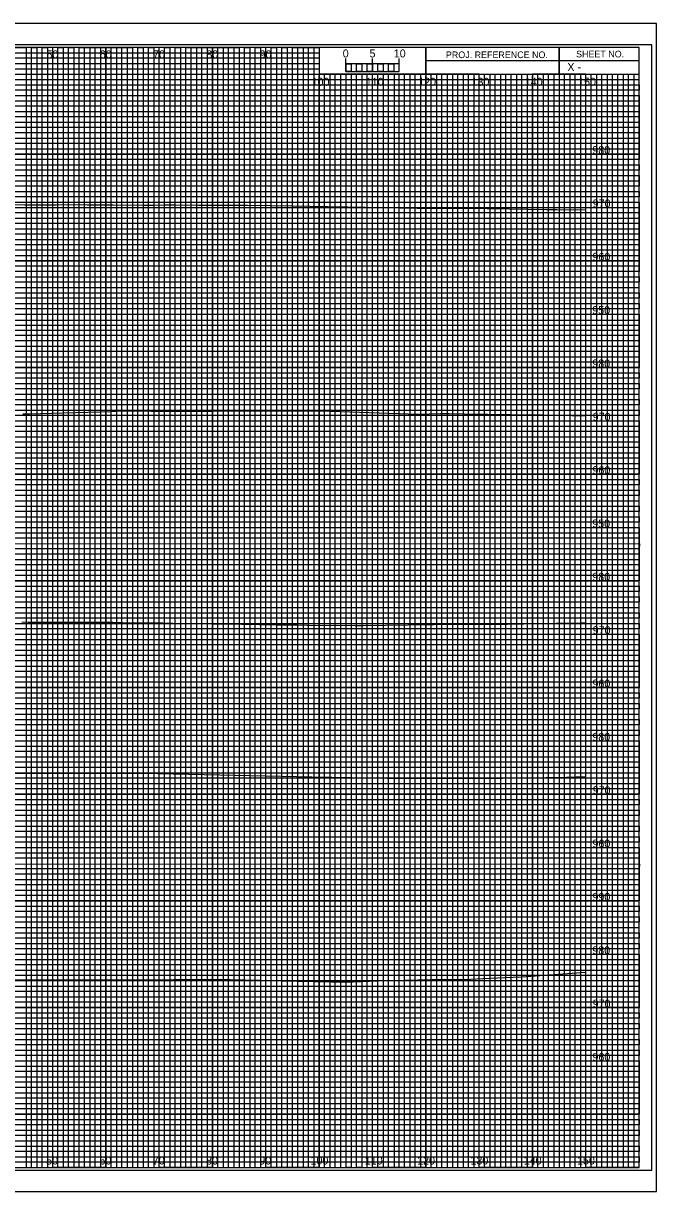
# Model space of a CAD drawing. Extents: x -13 to 760, y -5 to 1491.
# Drawn here: x 204.5 to 323.3, y 314.5 to 533.5 of the extents above; entities that cross this region are included whole.
import ezdxf

# ---------------------------------------------------------------- set-up
doc = ezdxf.new("R2010")
doc.units = 0
for name, color, linetype in [('Exist XS Ground Line', 7, 'Continuous'), ('Prop XS Elevation Labels', 7, 'Continuous'), ('Prop XS Offset Labels', 7, 'Continuous'), ('Sheet Cross Section CELL', 7, 'Continuous'), ('Sheet Cross Section Grid Major CELL', 7, 'Continuous'), ('Sheet Cross Section Grid Middle CELL', 7, 'Continuous'), ('Sheet Cross Section Grid Minor 1 CELL', 7, 'Continuous'), ('Sheet Cross Section Grid Minor 2 CELL', 7, 'Continuous'), ('Sheet Cross Section Scale CELL', 7, 'Continuous'), ('Sheet Cutting Line CELL', 7, 'Continuous'), ('Sheet DOT Grid CELL', 7, 'Continuous'), ('Sheet Plot Border Inside CELL', 7, 'Continuous'), ('Sheet Plot Border Outside CELL', 7, 'Continuous')]:
    doc.layers.add(name, color=color, linetype=linetype)

msp = doc.modelspace()

# ---------------------------------------------------------------- linework, layer by layer
at = {"layer": 'Exist XS Ground Line'}
for points in [[(202.88, 499.55), (204.75, 499.5), (206.74, 499.51), (210.68, 499.51), (214.94, 499.52), (216.5, 499.5), (217.94, 499.49), (219.17, 499.48), (220.13, 499.48), (221.36, 499.46), (226.92, 499.42), (229.08, 499.44), (231.04, 499.46), (232.82, 499.51), (237.39, 499.43), (241.03, 499.42), (243.02, 499.43), (243.42, 499.44), (246.57, 499.43), (255.04, 499.33), (261.56, 499.19), (265.31, 499.12), (271.92, 499.01), (278.4, 498.89), (282.15, 498.85), (291.48, 498.83), (292.39, 498.83), (295.64, 498.76), (302.62, 498.62), (304.57, 498.6), (310, 498.55)], [(202.88, 499.55), (204.75, 499.5), (206.74, 499.51), (210.68, 499.51), (214.94, 499.52), (216.5, 499.5), (217.94, 499.49), (219.17, 499.48), (220.13, 499.48), (221.36, 499.46), (226.92, 499.42), (229.08, 499.44), (231.04, 499.46), (232.82, 499.51), (237.39, 499.43), (241.03, 499.42), (243.02, 499.43), (243.42, 499.44), (246.57, 499.43), (255.04, 499.33), (261.56, 499.19), (265.31, 499.12), (271.92, 499.01), (278.4, 498.89), (282.15, 498.85), (291.48, 498.83), (292.39, 498.83), (295.64, 498.76), (302.62, 498.62), (304.57, 498.6), (310, 498.55)], [(204.4, 460.31), (205.65, 460.34), (209.75, 460.45), (218.84, 460.68), (220.94, 460.76), (223.32, 460.87), (224.87, 460.87), (226.48, 460.85), (228.46, 460.84), (229.33, 460.81), (229.71, 460.82), (231.78, 460.79), (237.68, 460.78), (239.04, 460.81), (240.03, 460.81), (260.29, 460.85), (278.51, 460.24), (282.74, 460.4), (284.4, 460.4), (287.25, 460.32), (295.94, 460.17), (297, 460.14), (297.06, 460.14), (297.47, 460.13), (297.58, 460.13), (299.47, 460.17), (310, 459.92)], [(204.4, 460.31), (205.65, 460.34), (209.75, 460.45), (218.84, 460.68), (220.94, 460.76), (223.32, 460.87), (224.87, 460.87), (226.48, 460.85), (228.46, 460.84), (229.33, 460.81), (229.71, 460.82), (231.78, 460.79), (237.68, 460.78), (239.04, 460.81), (240.03, 460.81), (260.29, 460.85), (278.51, 460.24), (282.74, 460.4), (284.4, 460.4), (287.25, 460.32), (295.94, 460.17), (297, 460.14), (297.06, 460.14), (297.47, 460.13), (297.58, 460.13), (299.47, 460.17), (310, 459.92)], [(204.23, 421.29), (205.43, 421.26), (206.07, 421.26), (208.42, 421.25), (210.37, 421.25), (220.94, 421.27), (221.29, 421.26), (223.07, 421.22), (230.67, 421.12), (234.42, 421.03), (240.01, 420.97), (242.02, 420.93), (248.71, 420.81), (252.08, 420.76), (255.81, 420.73), (257.74, 420.72), (266.77, 420.62), (268.1, 420.61), (268.11, 420.61), (268.22, 420.61), (276.66, 420.73), (279.91, 420.79), (281.51, 420.81), (289.1, 420.89), (289.26, 420.89), (289.67, 420.89), (294.57, 420.87), (295.35, 420.89), (301.54, 420.99), (304.46, 421.05), (309.11, 421.14), (310, 421.16)], [(204.23, 421.29), (205.43, 421.26), (206.07, 421.26), (208.42, 421.25), (210.37, 421.25), (220.94, 421.27), (221.29, 421.26), (223.07, 421.22), (230.67, 421.12), (234.42, 421.03), (240.01, 420.97), (242.02, 420.93), (248.71, 420.81), (252.08, 420.76), (255.81, 420.73), (257.74, 420.72), (266.77, 420.62), (268.1, 420.61), (268.11, 420.61), (268.22, 420.61), (276.66, 420.73), (279.91, 420.79), (281.51, 420.81), (289.1, 420.89), (289.26, 420.89), (289.67, 420.89), (294.57, 420.87), (295.35, 420.89), (301.54, 420.99), (304.46, 421.05), (309.11, 421.14), (310, 421.16)], [(202.25, 392.89), (210.98, 392.94), (212.48, 392.95), (213.44, 392.96), (222.72, 392.98), (226.78, 392.95), (241.38, 392.64), (258.63, 392.27), (269.93, 392.07), (272.7, 392.04), (274.73, 392.04), (284.13, 392.03), (289.5, 392.01), (294.36, 392.01), (302.58, 392.12), (304.6, 392.15), (310, 392.31)], [(202.25, 392.89), (210.98, 392.94), (212.48, 392.95), (213.44, 392.96), (222.72, 392.98), (226.78, 392.95), (241.38, 392.64), (258.63, 392.27), (269.93, 392.07), (272.7, 392.04), (274.73, 392.04), (284.13, 392.03), (289.5, 392.01), (294.36, 392.01), (302.58, 392.12), (304.6, 392.15), (310, 392.31)], [(202.9, 354.27), (210.32, 354.23), (213.14, 354.23), (223.26, 354.22), (223.36, 354.22), (223.38, 354.22), (223.39, 354.22), (232.69, 354.26), (234.72, 354.26), (241.91, 354.28), (243.31, 354.25), (248.98, 354.12), (249.03, 354.12), (252.97, 354.02), (262.33, 353.82), (262.78, 353.83), (266.38, 353.85), (270.96, 354.02), (280.98, 354.24), (282.58, 354.25), (288.37, 354.31), (290.72, 354.44), (294.85, 354.64), (297.94, 354.79), (310, 355.64)], [(202.9, 354.27), (210.32, 354.23), (213.14, 354.23), (223.26, 354.22), (223.36, 354.22), (223.38, 354.22), (223.39, 354.22), (232.69, 354.26), (234.72, 354.26), (241.91, 354.28), (243.31, 354.25), (248.98, 354.12), (249.03, 354.12), (252.97, 354.02), (262.33, 353.82), (262.78, 353.83), (266.38, 353.85), (270.96, 354.02), (280.98, 354.24), (282.58, 354.25), (288.37, 354.31), (290.72, 354.44), (294.85, 354.64), (297.94, 354.79), (310, 355.64)]]:
    msp.add_lwpolyline(points, dxfattribs=at)
at = {"layer": 'Sheet Cross Section CELL'}
for p, q in [((305, 529), (305, 524)), ((305, 524), (305, 529)), ((280, 526.5), (280, 524)), ((320, 526.49), (280, 526.49)), ((280, 524), (320, 524))]:
    msp.add_line(p, q, dxfattribs=at)
for points in [[(320, 529), (0, 529), (0, 319), (320, 319)], [(280, 529), (260, 529), (260, 524.03), (280, 524.03)], [(320, 529), (280, 529), (280, 524), (320, 524)]]:
    msp.add_lwpolyline(points, close=True, dxfattribs=at)
at = {"layer": 'Sheet Cross Section Grid Major CELL'}
for p, q in [((210, 529), (200, 529)), ((210, 319), (210, 529)), ((230, 529), (220, 529)), ((220, 529), (220, 319)), ((230, 319), (230, 529)), ((250, 529), (240, 529)), ((240, 529), (240, 319)), ((250, 319), (250, 529)), ((260, 529), (260, 319)), ((270, 319), (270, 524)), ((290, 524), (280, 524)), ((280, 524), (280, 319)), ((290, 319), (290, 524)), ((310, 524), (300, 524)), ((300, 524), (300, 319)), ((310, 319), (310, 524)), ((220, 319), (210, 319)), ((240, 319), (230, 319)), ((260, 319), (250, 319)), ((280, 319), (270, 319)), ((300, 319), (290, 319)), ((320, 319), (310, 319)), ((320, 319), (320, 319))]:
    msp.add_line(p, q, dxfattribs=at)
for points in [[(0, 519), (320, 519), (320, 509), (0, 509)], [(0, 499), (320, 499), (320, 489), (0, 489)], [(0, 479), (320, 479), (320, 469), (0, 469)], [(0, 459), (320, 459), (320, 449), (0, 449)], [(0, 439), (320, 439), (320, 429), (0, 429)], [(0, 419), (320, 419), (320, 409), (0, 409)], [(0, 399), (320, 399), (320, 389), (0, 389)], [(0, 379), (320, 379), (320, 369), (0, 369)], [(0, 359), (320, 359), (320, 349), (0, 349)], [(0, 339), (320, 339), (320, 329), (0, 329)]]:
    msp.add_lwpolyline(points, dxfattribs=at)
at = {"layer": 'Sheet Cross Section Grid Middle CELL'}
for points in [[(195, 529), (205, 529), (205, 319), (215, 319), (215, 529), (225, 529), (225, 319), (235, 319), (235, 529), (245, 529), (245, 319), (255, 319), (255, 529), (259.93, 529), (260, 529), (260, 524), (264.99, 524), (264.99, 319), (275, 319), (275, 524), (285, 524), (285, 319), (295, 319), (295, 524), (305, 524), (305, 319), (315, 319), (315, 524)], [(0, 524), (275, 524)], [(0, 504), (320, 504), (320, 514), (0, 514)], [(0, 484), (320, 484), (320, 494), (0, 494)], [(0, 464), (320, 464), (320, 474), (0, 474)], [(0, 444), (320, 444), (320, 454), (0, 454)], [(0, 424), (320, 424), (320, 434), (0, 434)], [(0, 404), (320, 404), (320, 414), (0, 414)], [(0, 384), (320, 384), (320, 394), (0, 394)], [(0, 364), (320, 364), (320, 374), (0, 374)], [(0, 344), (320, 344), (320, 354), (0, 354)], [(0, 324), (320, 324), (320, 334), (0, 334)]]:
    msp.add_lwpolyline(points, dxfattribs=at)
at = {"layer": 'Sheet Cross Section Grid Minor 1 CELL'}
for p, q in [((0, 528), (260, 528)), ((260, 528), (260, 526.98)), ((260, 526.98), (0, 526.98)), ((0, 526), (260, 526)), ((260, 526), (260, 524.89)), ((260, 524.89), (0, 524.89)), ((0, 523), (320, 523))]:
    msp.add_line(p, q, dxfattribs=at)
for points in [[(0, 522), (270, 522), (320, 522), (320, 521), (0, 521)], [(0, 520), (320, 520), (320, 518), (0, 518)], [(0, 517), (320, 517), (320, 516), (0, 515.98)], [(0, 515), (320, 515), (320, 513), (0, 513)], [(0, 512), (320, 512), (320, 511), (0, 511)], [(0, 510), (320, 510), (320, 508), (0, 508)], [(0, 507), (320, 507), (320, 506), (0, 506)], [(0, 505), (320, 505), (320, 503), (0, 503)], [(0, 502), (320, 502), (320, 501), (0, 501)], [(0, 500), (320, 500), (320, 498), (0, 498)], [(0, 497), (320, 497), (320, 496), (0, 496)], [(0, 495), (320, 495), (320, 492.95), (320, 492), (320, 491), (0, 491)], [(0, 493), (320, 493), (320, 492), (0, 492)], [(0, 490), (320, 490), (320, 488), (0, 488.03)], [(0, 488.03), (320, 488), (320, 487), (0, 487)], [(0, 486), (320, 486), (320, 485), (0, 485)], [(0, 483), (320, 483), (320, 482), (0, 482)], [(0, 481), (320, 481), (320, 480), (0, 480)], [(-0.07, 477.89), (320, 477.89), (320, 476.88), (-0.07, 476.88)], [(0, 476), (320, 476), (320, 475), (0, 475)], [(0, 473), (320, 473), (320, 472), (0, 472)], [(0, 471), (320, 471), (320, 470), (0, 470)], [(0, 468), (320, 468), (320, 467), (0, 467)], [(0, 466), (320, 466), (320, 465), (0, 465)], [(0, 463), (320, 463), (320, 462), (0, 462)], [(0, 461), (320, 461), (320, 460), (0, 460)], [(0, 458), (320, 458), (319.99, 456.98), (0, 457)], [(0, 456), (320, 456), (320, 455), (0, 455)], [(0, 453), (320, 453), (320, 452), (0, 452)], [(0, 451), (320, 451), (320, 450), (0, 450)], [(0, 448), (320, 448), (320, 447), (0, 447)], [(0, 446), (320, 446), (320, 445), (0, 445)], [(0, 443), (320, 443), (320, 442), (0, 442)], [(0, 441), (320, 441), (320, 440), (0, 440)], [(0, 438), (320, 438), (320, 437), (0, 437)], [(0, 435.99), (320.07, 435.91), (320, 435), (0, 435)], [(0, 433), (320, 433), (320, 432), (0, 432)], [(0, 431), (320, 431), (320, 430), (0, 430)], [(0, 428), (320, 428), (320, 427), (0, 427)], [(0, 426), (320, 426), (320, 425), (0, 425)], [(0, 423), (320, 423), (320, 422), (0, 422)], [(0, 421), (320, 421), (320, 420), (0, 420)], [(0, 418), (320, 418), (320, 417), (0, 417)], [(0, 416), (320, 416), (320, 415), (0, 415)], [(0, 413), (320, 413), (320, 412), (0, 412)], [(0, 411), (320, 411), (320, 410), (0, 410)], [(0, 408), (320, 408), (320, 407), (0, 407)], [(0, 406), (320, 406), (320, 405), (0, 405)], [(0, 403), (320, 403), (320, 402), (0, 402)], [(0, 401), (320, 401), (320, 400), (0, 400)], [(0, 398), (320, 398), (319.99, 396.98), (0, 397)], [(0, 396), (320, 396), (320, 395), (0, 395)], [(0, 393), (320, 393), (320, 392), (0, 392)], [(0, 391), (320, 391), (320, 390), (0, 390)], [(0, 388), (320, 388), (320, 387), (0, 387)], [(0, 386), (320, 386), (320, 385), (0, 385)], [(0, 383), (320, 383), (320, 382), (0, 382)], [(0, 381), (320, 381), (320, 380), (0, 380)], [(0, 378), (320, 378), (320, 377), (0, 377)], [(0, 375.99), (320.07, 375.91), (320, 375), (0, 375)], [(0, 373), (320, 373), (320, 372), (0, 372)], [(0, 371), (320, 371), (320, 370), (0, 370)], [(0, 368), (320, 368), (320, 367), (0, 367)], [(0, 366), (320, 366), (320, 365), (0, 365)], [(0, 363), (320, 363), (320, 362), (0, 362)], [(0, 361), (320, 361), (320, 360), (0, 360)], [(0, 358), (320, 358), (320, 357), (0, 357)], [(0, 356), (320, 356), (320, 355), (0, 355)], [(0, 353), (320, 353), (320, 352), (0, 352)], [(0, 351), (320, 351), (320, 350), (0, 350)], [(0, 348), (320, 348), (320, 347), (0, 347)], [(0, 346), (320, 346), (320, 345), (0, 345)], [(0, 343), (320, 343), (320, 342), (0, 342)], [(0, 341), (320, 341), (320, 340), (0, 340)], [(0, 338), (320, 338), (320, 337), (0, 337)], [(0, 336), (320, 336), (320, 335), (0, 335)], [(0, 333), (320, 333), (320, 332), (0, 332)], [(0, 331), (320, 331), (320, 330), (0, 330)], [(0, 328), (320, 328), (320, 327), (0, 327)], [(0, 326), (320, 326), (320, 325), (0, 325)], [(0, 323), (320, 323), (320, 322), (0, 322)], [(0, 321), (320, 321), (320, 320), (0, 320)]]:
    msp.add_lwpolyline(points, dxfattribs=at)
at = {"layer": 'Sheet Cross Section Grid Minor 2 CELL'}
for p, q in [((267, 524), (266.01, 524)), ((266.01, 524), (266.01, 319)), ((267, 319), (267, 524)), ((269, 524), (268, 524)), ((268, 524), (268, 319)), ((269, 319), (269, 524)), ((266.01, 319), (265, 319)), ((268, 319), (267, 319))]:
    msp.add_line(p, q, dxfattribs=at)
for points in [[(205, 319), (206, 319), (206, 529), (207, 529), (207, 319)], [(207, 319), (208, 319), (208, 529), (209, 529), (209, 319)], [(210, 319), (211, 319), (211, 529), (212, 529), (212, 319)], [(212, 319), (213, 319), (213, 529), (214, 529), (214, 319)], [(215, 319), (216, 319), (216, 529), (217, 529), (217, 319)], [(217, 319), (218, 319), (218, 529), (219, 529), (219, 319)], [(220, 319), (221, 319), (221, 529), (222, 529), (222, 319)], [(222, 319), (223, 319), (223, 529), (224, 529), (224, 319)], [(225, 319), (226, 319), (226, 529), (227, 529), (227, 319)], [(227, 319), (228, 319), (228, 529), (229, 529), (229, 319)], [(230, 319), (231, 319), (231, 529), (232, 529), (232, 319)], [(232, 319), (233, 319), (233, 529), (234, 529), (234, 319)], [(235, 319), (236, 319), (236, 529), (237, 529), (237, 319)], [(237, 319), (238, 319), (238, 529), (239, 529), (239, 319)], [(240, 319), (241, 319), (241, 529), (242, 529), (242, 319)], [(242, 319), (243, 319), (243, 529), (244, 529), (244, 319)], [(245, 319), (246, 319), (246, 529), (247, 529), (247, 319)], [(247, 319), (248, 319), (248, 529), (249, 529), (249, 319)], [(250, 319), (251, 319), (251, 529), (252, 529), (252, 319)], [(252, 319), (253, 319), (253, 529), (254, 529), (254, 319)], [(255, 319), (256, 319), (256, 529), (257, 529), (257, 319)], [(257, 319), (258, 319), (258, 529), (259, 529), (259, 319)], [(260, 319), (261, 319), (261, 524), (262.02, 524), (262.02, 319)], [(262, 319), (263, 319), (263, 524), (263.99, 524), (263.99, 319)], [(270, 319), (270.98, 319), (270.98, 524), (272, 524), (272, 319)], [(272, 319), (273, 319), (273, 524), (274.05, 524), (274.05, 319)], [(275, 319), (276, 319), (276, 524), (277, 524), (277, 319)], [(277, 319), (278, 319), (278, 524), (279, 524), (279, 319)], [(280, 319), (281, 319), (281, 524), (282, 524), (282, 319)], [(282, 319), (283, 319), (283, 524), (284, 524), (284, 319)], [(285, 319), (286, 319), (286, 524), (287, 524), (287, 319)], [(287, 319), (288, 319), (288, 524), (289, 524), (289, 319)], [(290, 319), (291, 319), (291, 524), (292, 524), (292, 319)], [(292, 319), (293, 319), (293, 524), (294, 524), (294, 319)], [(295, 319), (296, 319), (296, 524), (297, 524), (297, 319)], [(297, 319), (298, 319), (298, 524), (299, 524), (299, 319)], [(300, 319), (301, 319), (301, 524), (302, 524), (302, 319)], [(302, 319), (303, 319), (303, 524), (304, 524), (304, 319)], [(305, 319), (306, 319), (306, 524), (307, 524), (307, 319)], [(307, 319), (308, 319), (308, 524), (309, 524), (309, 319)], [(310, 319), (311, 319), (311, 524), (312, 524), (312, 319)], [(312, 319), (313, 319), (313, 524), (314, 524), (314, 319)], [(315, 319), (316, 319), (316, 524), (317, 524), (317, 319)], [(317, 319), (318, 319), (318, 524), (319, 524), (319, 319)]]:
    msp.add_lwpolyline(points, dxfattribs=at)
at = {"layer": 'Sheet Cross Section Scale CELL'}
for p, q in [((265, 524.49), (265, 526.9)), ((265, 525.9), (265, 526.9)), ((270, 524.49), (270, 526.9)), ((275, 524.49), (275, 526.9)), ((275, 525.9), (275, 526.9))]:
    msp.add_line(p, q, dxfattribs=at)
for points in [[(275, 525.9), (265, 525.9), (265, 524.49), (275, 524.49)], [(265, 525.9), (266, 525.9), (266, 524.49), (265, 524.49)], [(267, 525.9), (268, 525.9), (268, 524.49), (267, 524.49)], [(269, 525.9), (270, 525.9), (270, 524.49), (269, 524.49)], [(271, 525.9), (272, 525.9), (272, 524.49), (271, 524.49)], [(273, 525.9), (274, 525.9), (274, 524.49), (273, 524.49)]]:
    msp.add_lwpolyline(points, close=True, dxfattribs=at)
at = {"layer": 'Sheet Cutting Line CELL'}
for p, q in [((323.3, 533.5), (-13.4, 533.5)), ((-13.4, 314.5), (323.3, 314.5))]:
    msp.add_line(p, q, dxfattribs=at)
at = {"layer": 'Sheet DOT Grid CELL'}
for p, q in [((210, 319), (210, 529)), ((220, 319), (220, 529)), ((230, 319), (230, 529)), ((240, 319), (240, 529)), ((250, 319), (250, 529)), ((260, 319), (260, 523.69)), ((270, 319), (270, 523.69)), ((280, 319), (280, 523.69)), ((290, 319), (290, 523.69)), ((300, 319), (300, 523.69)), ((310, 319), (310, 523.69)), ((0, 519), (320, 519)), ((0, 509), (320, 509)), ((0, 499), (320, 499)), ((0, 489), (320, 489)), ((0, 479), (320, 479)), ((0, 469), (320, 469)), ((0, 459), (320, 459)), ((0, 449), (320, 449)), ((0, 439), (320, 439)), ((0, 429), (320, 429)), ((0, 419), (320, 419)), ((0, 409), (320, 409)), ((0, 399), (320, 399)), ((0, 389), (320, 389)), ((0, 379), (320, 379)), ((0, 369), (320, 369)), ((0, 359), (320, 359)), ((0, 349), (320, 349)), ((0, 339), (320, 339)), ((0, 329), (320, 329))]:
    msp.add_line(p, q, dxfattribs=at)
at = {"layer": 'Sheet Plot Border Inside CELL'}
msp.add_lwpolyline([(-10.8, 318.5), (322.4, 318.5), (322.4, 529.5), (-10.8, 529.5)], close=True, dxfattribs=at)
at = {"layer": 'Sheet Plot Border Outside CELL'}
msp.add_lwpolyline([(-13.4, 314.5), (323.3, 314.5), (323.3, 533.5), (-13.4, 533.5)], close=True, dxfattribs=at)

# ---------------------------------------------------------------- texts
at = {"layer": 'Prop XS Elevation Labels'}
for s, p in [('980', (311.24, 509)), ('970', (311.3, 499)), ('960', (311.26, 489)), ('950', (311.22, 479)), ('980', (311.24, 469)), ('970', (311.3, 459)), ('960', (311.26, 449)), ('950', (311.22, 439)), ('980', (311.24, 429)), ('970', (311.3, 419)), ('960', (311.26, 409)), ('980', (311.24, 399)), ('970', (311.3, 389)), ('960', (311.26, 379)), ('990', (311.26, 369)), ('980', (311.24, 359)), ('970', (311.3, 349)), ('960', (311.26, 339))]:
    msp.add_text(s, height=1.5, dxfattribs=at).set_placement(p)
at = {"layer": 'Prop XS Offset Labels'}
for s, p in [('50', (208.83, 526.94)), ('60', (218.83, 526.94)), ('70', (228.83, 526.94)), ('80', (238.83, 526.94)), ('90', (248.83, 526.94)), ('100', (258.57, 521.8)), ('110', (268.75, 521.8)), ('120', (278.57, 521.8)), ('130', (288.57, 521.8)), ('140', (298.57, 521.8)), ('150', (308.57, 521.8)), ('50', (208.78, 319.59)), ('60', (218.78, 319.59)), ('70', (228.78, 319.59)), ('80', (238.78, 319.59)), ('90', (248.78, 319.59)), ('100', (258.37, 319.59)), ('110', (268.55, 319.59)), ('120', (278.37, 319.59)), ('130', (288.37, 319.59)), ('140', (298.37, 319.59)), ('150', (308.37, 319.59))]:
    msp.add_text(s, height=1.5, dxfattribs=at).set_placement(p)
at = {"layer": 'Sheet Cross Section CELL'}
for s, height, p in [('PROJ. REFERENCE NO.', 1.25, (283.77, 526.99)), ('SHEET NO.', 1.25, (308.19, 527.12)), ('X - ', 1.5, (306.55, 524.57))]:
    msp.add_text(s, height=height, dxfattribs=at).set_placement(p)
at = {"layer": 'Sheet Cross Section Scale CELL'}
for s, p in [('0', (264.41, 527.12)), ('5', (269.44, 527.12)), ('10', (273.99, 527.12))]:
    msp.add_text(s, height=1.5, dxfattribs=at).set_placement(p)

doc.saveas('drawing.dxf')
